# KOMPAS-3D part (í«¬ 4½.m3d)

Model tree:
1. Эскиз:1
2. Операция выдавливания:1
     Расстояние 1 = 2
3. Эскиз:2
4. Операция выдавливания:2
     Расстояние 1 = 5
5. Эскиз:3
6. Операция выдавливания:3
     Расстояние 1 = 2
7. Эскиз:4
8. Операция выдавливания:4
     Расстояние 1 = 60
9. Эскиз:5
10. Операция выдавливания:5
     Расстояние 1 = 2
11. Эскиз:6
12. Операция выдавливания:6
     Расстояние 1 = 4.5
13. Эскиз:7
14. Операция выдавливания:7
     Расстояние 1 = 2
15. Скругление:1
     Радиус = 1
16. Скругление:2
     Радиус = 1
17. Эскиз:8
18. Вырезать элемент выдавливания:1
     Расстояние 1 = 10; Угол 1 = 35
19. Эскиз:9
20. Вырезать элемент выдавливания:2
     Расстояние 1 = 10; Угол 1 = 35
21. Эскиз:10
22. Вырезать элемент выдавливания:3
     Расстояние 2 = 22; Расстояние 1 = 22; Угол 1 = 35
23. Эскиз:11
24. Вырезать элемент выдавливания:4
     Расстояние 2 = 2; Расстояние 1 = 2
25. Эскиз:12
26. Вырезать элемент выдавливания:5
     Расстояние 2 = 2; Расстояние 1 = 2; Угол 1 = 35
27. Эскиз:13
28. Вырезать элемент выдавливания:6
     Расстояние 2 = 2; Расстояние 1 = 122
29. Эскиз:15
30. Операция выдавливания:9
     Расстояние 1 = 10; Расстояние 2 = 0.5
